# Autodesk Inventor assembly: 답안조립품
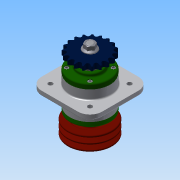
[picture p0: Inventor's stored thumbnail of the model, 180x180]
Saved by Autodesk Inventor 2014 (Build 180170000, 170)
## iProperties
Created: 2015-09
Part Number: 답안조립품
Document SubType Name: Assembly
Designer: study
Author: study
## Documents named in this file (12)
- C:\Users\study\Desktop\450909V1016\답안조립품.iam
- C:\Users\study\Desktop\450909V1016\1-본체.ipt
- C:\Users\study\Desktop\450909V1016\3-축.ipt
- C:\Users\study\Desktop\450909V1016\4-V벨트풀리.ipt
- C:\Users\study\Desktop\450909V1016\5-체인 스프로킷.ipt
- C:\Users\study\Desktop\450909V1016\7-부시.ipt
- C:\Users\study\Desktop\450909V1016\2-커버.ipt
- C:\Users\study\Desktop\450909V1016\6-베어링 6206.ipt
- C:\Users\study\Desktop\450909V1016\8-오일실 30x42.ipt
- C:\Users\study\Desktop\450909V1016\11-키 6x6.ipt
- C:\Users\study\Desktop\450909V1016\9-M16-너트.ipt
- C:\Users\study\Desktop\450909V1016\10-M6.ipt
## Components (23 placed, 11 different names)
1. 1-본체:1
2. 3-축:1 — 각도:1, 각도:2
3. 4-V벨트풀리:1 — 각도:4, 각도:5
4. 5-체인 스프로킷:1 — 각도:3, 각도:6
5. 7-부시:1
6. 2-커버:1
7. 6-베어링 6206:1
8. 8-8-오일실 30x42:1
9. 2-커버:2
10. 6-베어링 6206:2
11. 8-8-오일실 30x42:2
12. 11-키 6x6:1 — 각도:2, 각도:3
13. 11-키 6x6:2 — 각도:1, 각도:4
14. 9-M16 너트:1 — 각도:5
15. 9-M16 너트:2 — 각도:6
16. 10-M6:1
17. 10-M6:2
18. 10-M6:3
19. 10-M6:4
20. 10-M6:5
21. 10-M6:6
22. 10-M6:7
23. 10-M6:8
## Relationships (6: Angle 6)
- 각도:1 [Angle]: 3-축:1 ↔ 11-키 6x6:2
- 각도:2 [Angle]: 3-축:1 ↔ 11-키 6x6:1
- 각도:3 [Angle]: 5-체인 스프로킷:1 ↔ 11-키 6x6:1
- 각도:4 [Angle]: 4-V벨트풀리:1 ↔ 11-키 6x6:2
- 각도:5 [Angle]: 4-V벨트풀리:1 ↔ 9-M16 너트:1
- 각도:6 [Angle]: 5-체인 스프로킷:1 ↔ 9-M16 너트:2
